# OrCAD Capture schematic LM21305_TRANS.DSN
size Custom; title: LM21305 3-V to 18-V, 5-A Adjustable Frequency; rev: 1.1; note: Datasheet: SNVS639G  EVM:SNVA432D
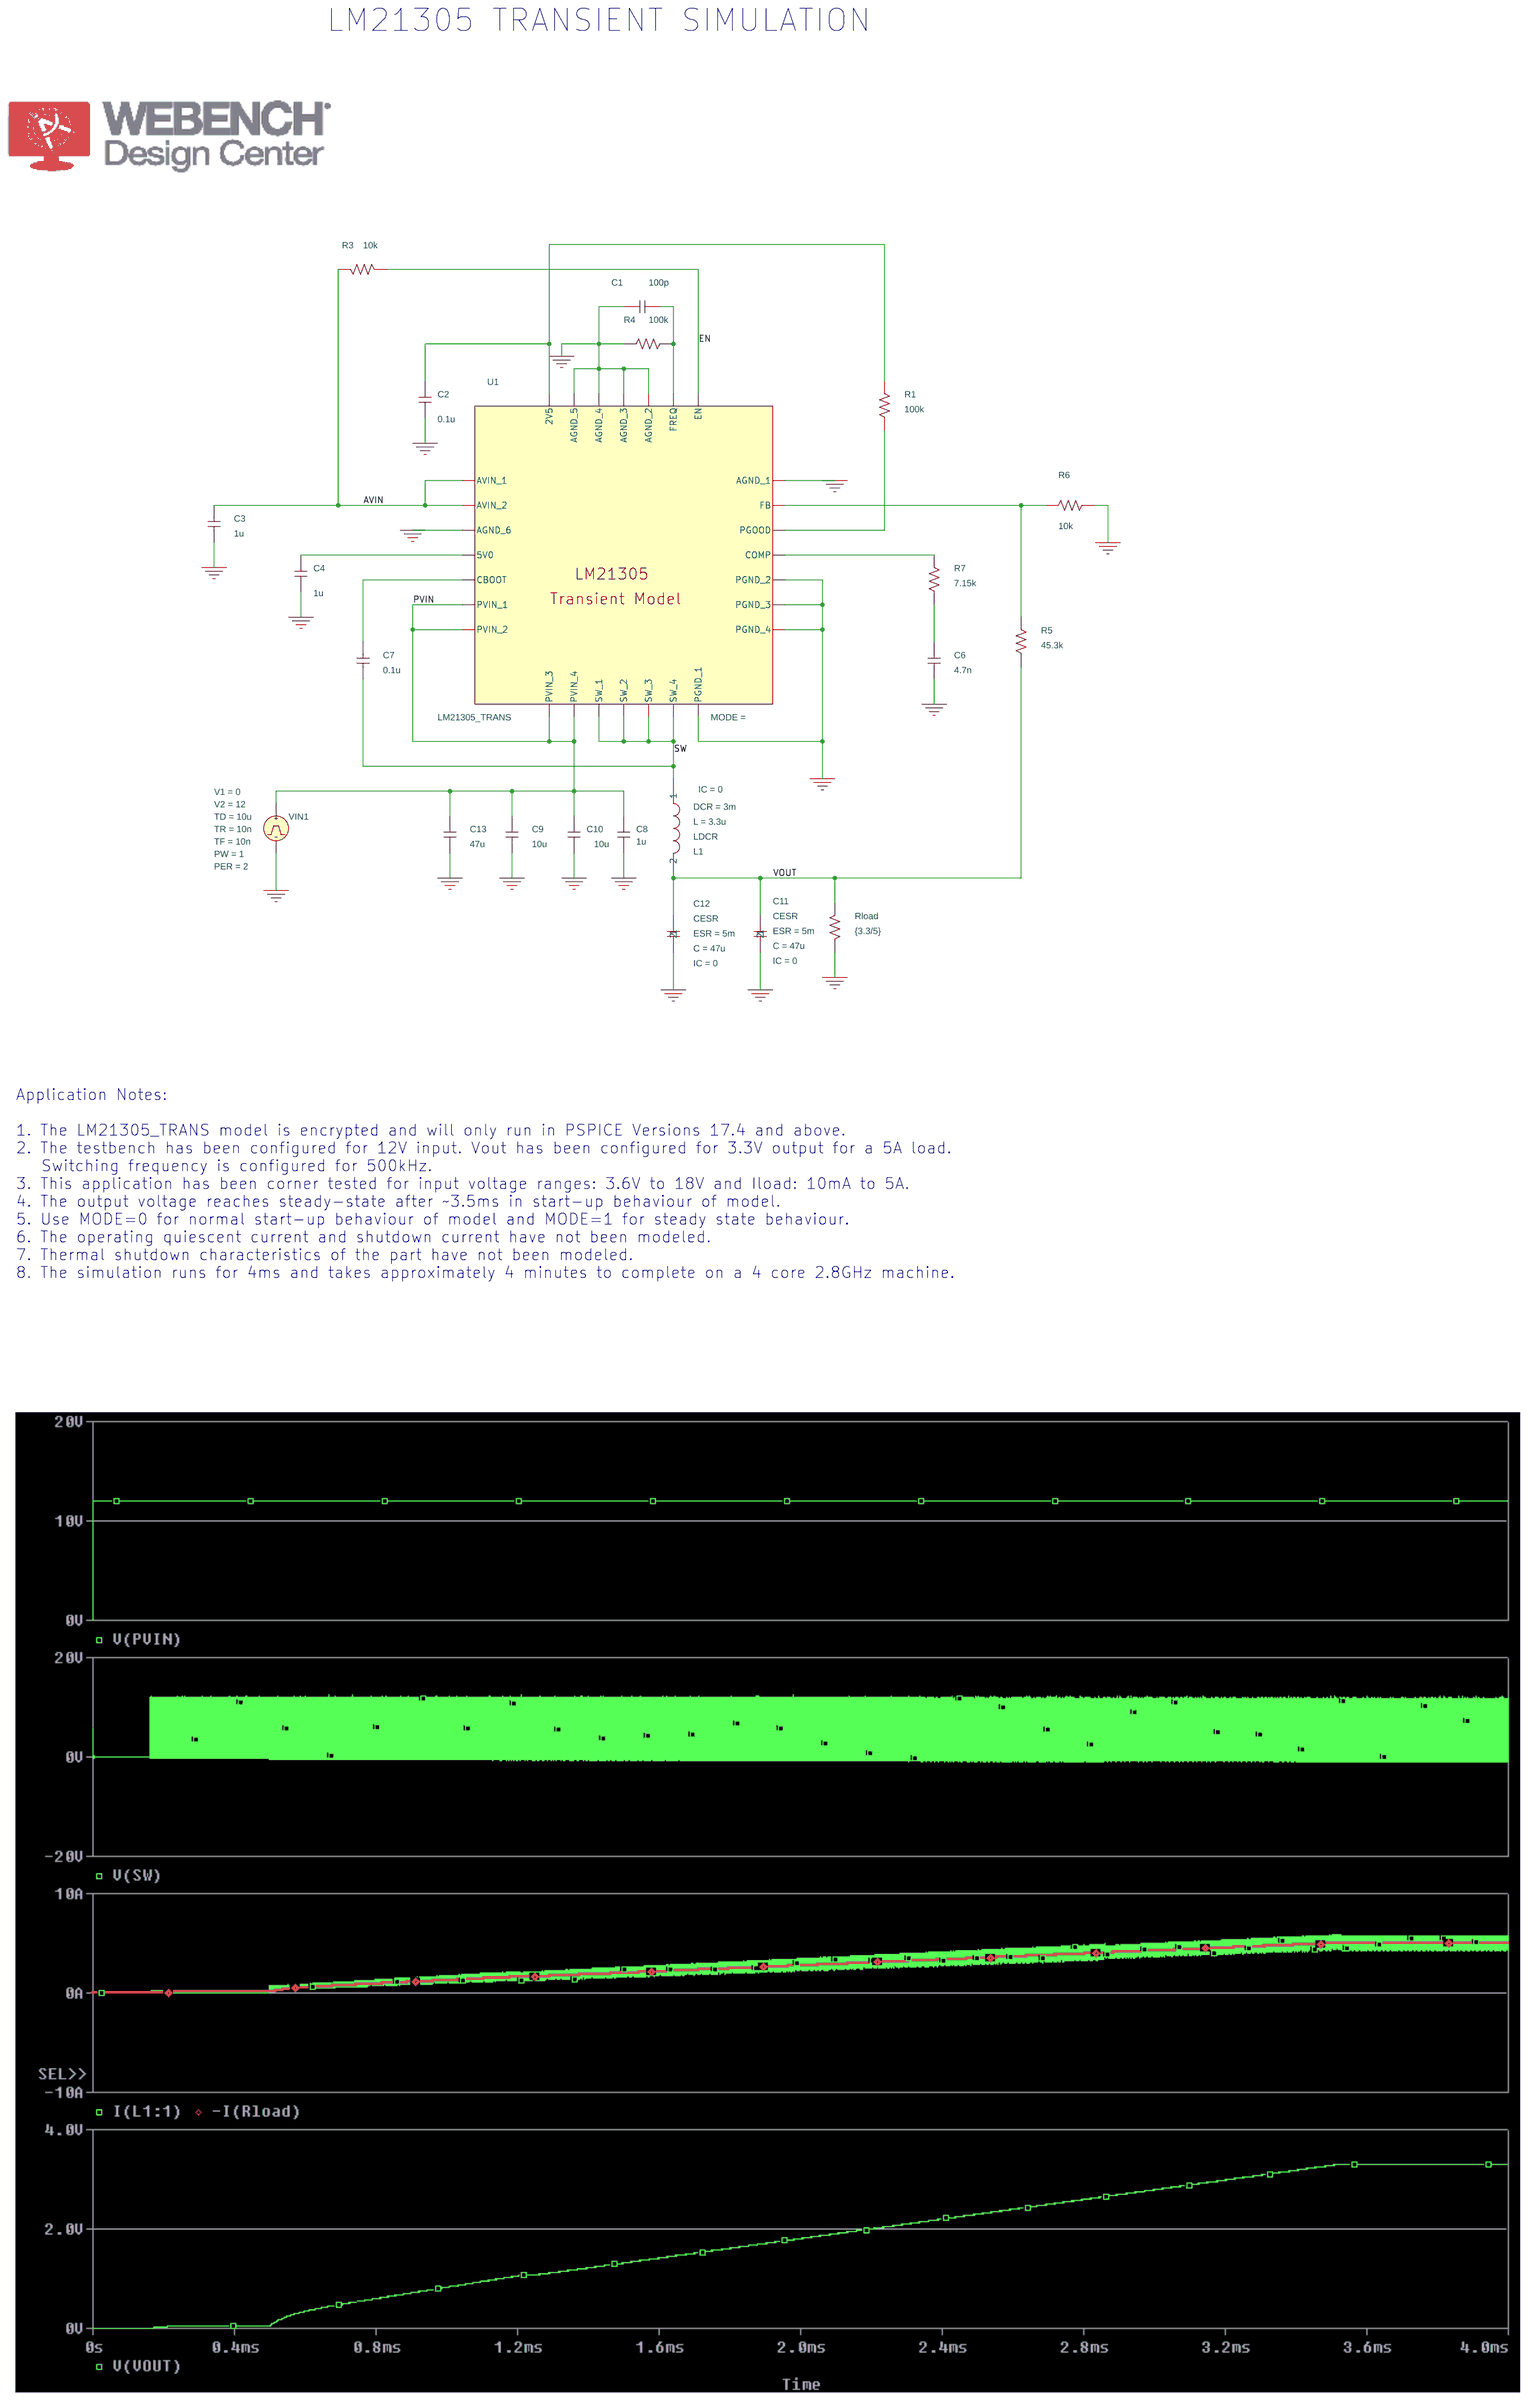
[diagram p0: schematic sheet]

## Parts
C1  100p  [RAD/CK05]
C2  0.1u  [RAD/CK05]
C3  1u  [RAD/CK05]
C4  1u  [RAD/CK05]
C6  4.7n  [RAD/CK05]
C7  0.1u  [RAD/CK05]
C8  1u  [RAD/CK05]
C9  10u  [RAD/CK05]
C10  10u  [RAD/CK05]
C11  CESR
C12  CESR
C13  47u  [RAD/CK05]
L1  LDCR
R1  100k  [AX/RC05]
R3  10k  [AX/RC05]
R4  100k  [AX/RC05]
R5  45.3k  [AX/RC05]
R6  10k  [AX/RC05]
R7  7.15k  [AX/RC05]
Rload  {3.3/5}  [AX/RC05]
U1  LM21305_TRANS
VIN1  VPULSE

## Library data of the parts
C1-C4 C6-C10 C13 = C
C11 = CESR: C: 47u; ESR: 5m; IC: 0; PSpiceTemplate: X^@REFDES %1 %2 @MODEL PARAMS: ?C|C=@C||C=10U| ?ESR|ESR=@ESR||ESR=2M| ?IC|IC=@IC||IC=0|
C12 = CESR_1: C: 47u; ESR: 5m; IC: 0; PSpiceTemplate: X^@REFDES %1 %2 @MODEL PARAMS: ?C|C=@C||C=10U| ?ESR|ESR=@ESR||ESR=2M| ?IC|IC=@IC||IC=0|
L1 = LDCR: DCR: 3m; IC: 0; L: 3.3u; PSpiceTemplate: X^@REFDES %1 %2 @MODEL PARAMS: ?L|L=@L||L=10U| ?DCR|DCR=@DCR||DCR=20M| ?IC|IC=@IC||IC=0|
R1 R3-R7 Rload = R
U1 = LM21305
VIN1 = VPULSE: PER: 2; PW: 1; TD: 10u; TF: 10n; TR: 10n; V1: 0; V2: 12

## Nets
AVIN: C3.2 R3.2 U1.AVIN_1 U1.AVIN_2
PVIN: C8.2 C9.2 C10.2 C13.2 U1.PVIN_1 U1.PVIN_2 U1.PVIN_3 U1.PVIN_4 VIN1.1(+)
0: C1.2 C2.1 C3.1 C4.1 C6.1 C8.1 C9.1 C10.1 C11.2 C12.2 C13.1 R4.2 R6.1 Rload.1 U1.AGND_1 U1.AGND_2 U1.AGND_3 U1.AGND_4 U1.AGND_5 U1.AGND_6 U1.PGND_1 U1.PGND_2 U1.PGND_3 U1.PGND_4 VIN1.2(-)
EN: R3.1 U1.EN
SW: C7.2 L1.1 U1.SW_1 U1.SW_2 U1.SW_3 U1.SW_4
VOUT: C11.1 C12.1 L1.2 R5.1 Rload.2
N14366596: C4.2 U1.5V0
N14366774: C2.2 R1.2 U1.2V5
N14367382: R7.2 U1.COMP
N14367416: R5.2 R6.2 U1.FB
N14367504: C1.1 R4.1 U1.FREQ
N14367660: R1.1 U1.PGOOD
N14367712: C7.1 U1.CBOOT
N14381447: C6.2 R7.1

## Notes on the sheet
- LM21305 TRANSIENT SIMULATION
- Application Notes:
  1. The LM21305_TRANS model is encrypted and will only run in PSPICE Versions 17.4 and above.
  2. The testbench has been configured for 12V input. Vout has been configured for 3.3V output for a 5A load.
     Switching frequency is configured for 500kHz.
  3. This application has been corner tested for input voltage ranges: 3.6V to 18V and Iload: 10mA to 5A.
  4. The output voltage reaches steady-state after ~3.5ms in start-up behaviour of model.
  5. Use MODE=0 for normal start-up behaviour of model and MODE=1 for steady state behaviour.
  6. The operating quiescent current and shutdown current have not been modeled.
  7. Thermal shutdown characteristics of the part have not been modeled.
  8. The simulation runs for 4ms and takes approximately 4 minutes to complete on a 4 core 2.8GHz machine.
